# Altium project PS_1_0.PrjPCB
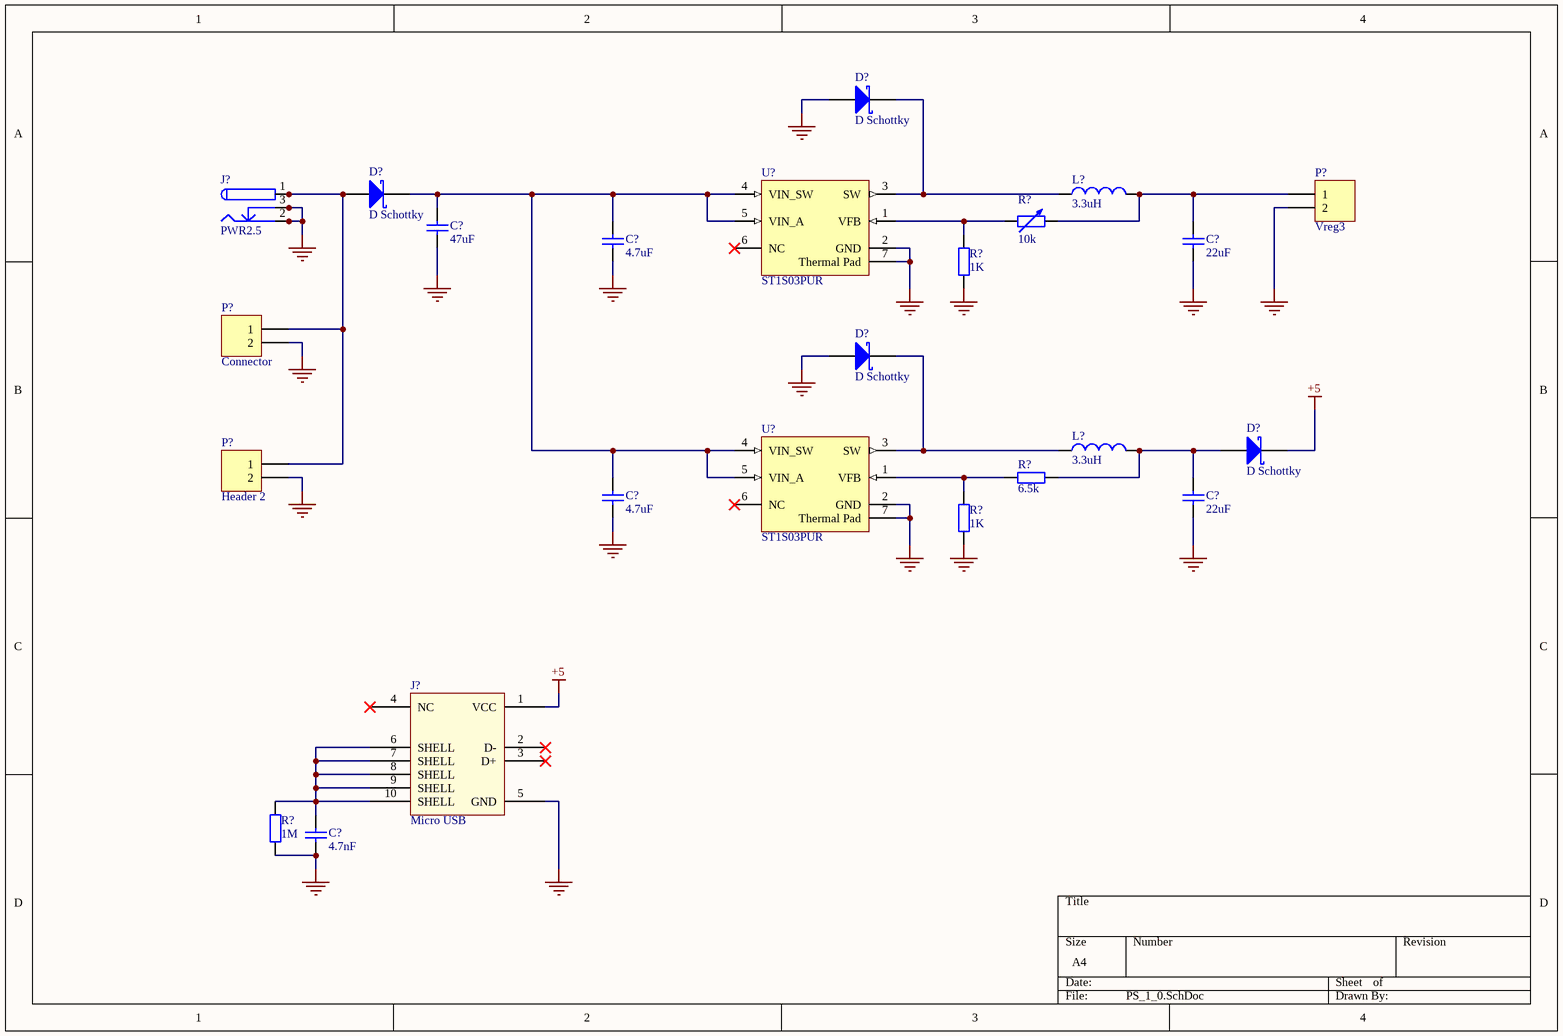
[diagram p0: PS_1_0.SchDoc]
2 sheets, 39 parts. Net scope: global (net labels, ports and power ports of the same name join across sheets).
Sheets:
  PS_1_0.SchDoc
  PS_1_0_s2.SchDoc

## Sheet PS_1_0.SchDoc
size A4

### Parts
(Parts that share a designator on the sheet are numbered #1, #2 ... from top to bottom, then left to right.)
C?#1  47uF  [C0805]
C?#2  4.7uF  [C0805]
C?#3  22uF  [C0805]
C?#4  4.7uF  [C0805]
C?#5  22uF  [C0805]
C?#6  4.7nF  [0603]
D?#1  D Schottky  [SMB]
D?#2  D Schottky  [SMB]
D?#3  D Schottky  [SMB]
D?#4  D Schottky  [SMB]
J?#1  PWR2.5  [KLD-0202]
J?#2  Micro USB
L?#1  3.3uH  [0402-A]
L?#2  3.3uH  [0402-A]
P?#1  Vreg3  [HDR1X2]
P?#2  Connector  [L_ZAC]
P?#3  Header 2  [HDR1X2]
R?#1  10k  [AXIAL-0.6]
R?#2  1K  [0603]
R?#3  6.5k  [0603]
R?#4  1K  [0603]
R?#5  1M  [0603]
U?#1  ST1S03PUR  [DFN6D_M]
U?#2  ST1S03PUR  [DFN6D_M]

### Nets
+5: D?#4.2(K) J?#2.1(VCC)
GND: C?#1.2 C?#2.2 C?#3.2 C?#4.2 C?#5.2 C?#6.2 D?#1.1(A) D?#3.1(A) J?#1.2 J?#1.2A J?#1.2B J?#1.3 J?#1.3A J?#1.3B J?#2.5(GND) P?#1.2 P?#2.2 P?#3.2 R?#2.1 R?#4.1 R?#5.1 U?#1.2(GND) U?#1.7(Thermal_Pad) U?#2.2(GND) U?#2.7(Thermal_Pad)
NetC?#1_1: C?#1.1 C?#2.1 C?#4.1 D?#2.2(K) U?#1.4(VIN_SW) U?#1.5(VIN_A) U?#2.4(VIN_SW) U?#2.5(VIN_A)
NetC?#3_1: C?#3.1 L?#1.2 P?#1.1 R?#1.2
NetC?#5_1: C?#5.1 D?#4.1(A) L?#2.2 R?#3.1
NetC?#6_1: C?#6.1 J?#2.6(SHELL) J?#2.7(SHELL) J?#2.8(SHELL) J?#2.9(SHELL) J?#2.10(SHELL) R?#5.2
NetD?#1_2: D?#1.2(K) L?#1.1 U?#1.3(SW)
NetD?#2_1: D?#2.1(A) J?#1.1 J?#1.1A J?#1.1B P?#2.1 P?#3.1
NetD?#3_2: D?#3.2(K) L?#2.1 U?#2.3(SW)
NetR?#1_1: R?#1.1 R?#2.2 U?#1.1(VFB)
NetR?#3_2: R?#3.2 R?#4.2 U?#2.1(VFB)

Not connected (* = marked no-connect by the designer): J?#2 2(D-)* 3(D+)* 4(NC)*; U?#1 6(NC)*; U?#2 6(NC)*

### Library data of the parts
C?#1-C?#6 = Cap Semi: Capacitor (Semiconductor SIM Model)
D?#1-D?#4 = D Schottky: Schottky Diode
J?#1 = PWR2.5: Low Voltage Power Supply Connector
J?#2 = Micro USB: type B
L?#1 L?#2 = Inductor: Code_IEC: 1005
P?#1-P?#3 = Header 2: Header, 2-Pin
R?#1 = Res Adj2: Variable Resistor; Set Position: 0.5
R?#2-R?#5 = Res2: Resistor
U?#1 U?#2 = ST1S03PUR: 1.5 A, 1.5 MHz adjustable, step-down switching regulator, DFN6D

## Sheet PS_1_0_s2.SchDoc
size A4
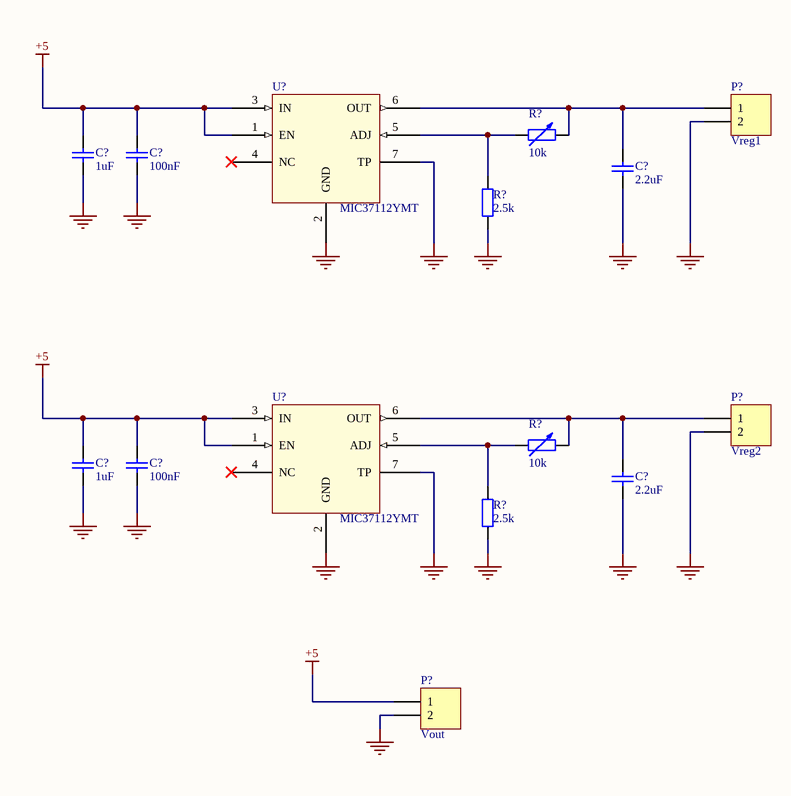
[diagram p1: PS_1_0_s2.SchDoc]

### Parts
(Parts that share a designator on the sheet are numbered #1, #2 ... from top to bottom, then left to right.)
C?#7  1uF  [0603]
C?#8  100nF  [0603]
C?#9  2.2uF  [0603]
C?#10  1uF  [0603]
C?#11  100nF  [0603]
C?#12  2.2uF  [0603]
P?#4  Vreg1  [HDR1X2]
P?#5  Vreg2  [HDR1X2]
P?#6  Vout  [HDR1X2]
R?#6  10k  [AXIAL-0.6]
R?#7  2.5k  [0603]
R?#8  10k  [AXIAL-0.6]
R?#9  2.5k  [0603]
U?#3  MIC37112YMT
U?#4  MIC37112YMT

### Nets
+5: C?#7.1 C?#8.1 C?#10.1 C?#11.1 P?#6.1 U?#3.1(EN) U?#3.3(IN) U?#4.1(EN) U?#4.3(IN)
GND: C?#7.2 C?#8.2 C?#9.2 C?#10.2 C?#11.2 C?#12.2 P?#4.2 P?#5.2 P?#6.2 R?#7.1 R?#9.1 U?#3.2(GND) U?#3.7(TP) U?#4.2(GND) U?#4.7(TP)
NetC?#9_1: C?#9.1 P?#4.1 R?#6.2 U?#3.6(OUT)
NetC?#12_1: C?#12.1 P?#5.1 R?#8.2 U?#4.6(OUT)
NetR?#6_1: R?#6.1 R?#7.2 U?#3.5(ADJ)
NetR?#8_1: R?#8.1 R?#9.2 U?#4.5(ADJ)

Not connected (* = marked no-connect by the designer): U?#3 4(NC)*; U?#4 4(NC)*

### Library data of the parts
C?#7-C?#12 = Cap Semi: Capacitor (Semiconductor SIM Model)
P?#4-P?#6 = Header 2: Header, 2-Pin
R?#6 R?#8 = Res Adj2: Variable Resistor; Set Position: 0.5
R?#7 R?#9 = Res2: Resistor
U?#3 U?#4 = MIC37112YMT: LDO, 1A

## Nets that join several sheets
+5: PS_1_0 (D?#4.2 J?#2.1), PS_1_0_s2 (9 pins)
GND: PS_1_0 (25 pins), PS_1_0_s2 (15 pins)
